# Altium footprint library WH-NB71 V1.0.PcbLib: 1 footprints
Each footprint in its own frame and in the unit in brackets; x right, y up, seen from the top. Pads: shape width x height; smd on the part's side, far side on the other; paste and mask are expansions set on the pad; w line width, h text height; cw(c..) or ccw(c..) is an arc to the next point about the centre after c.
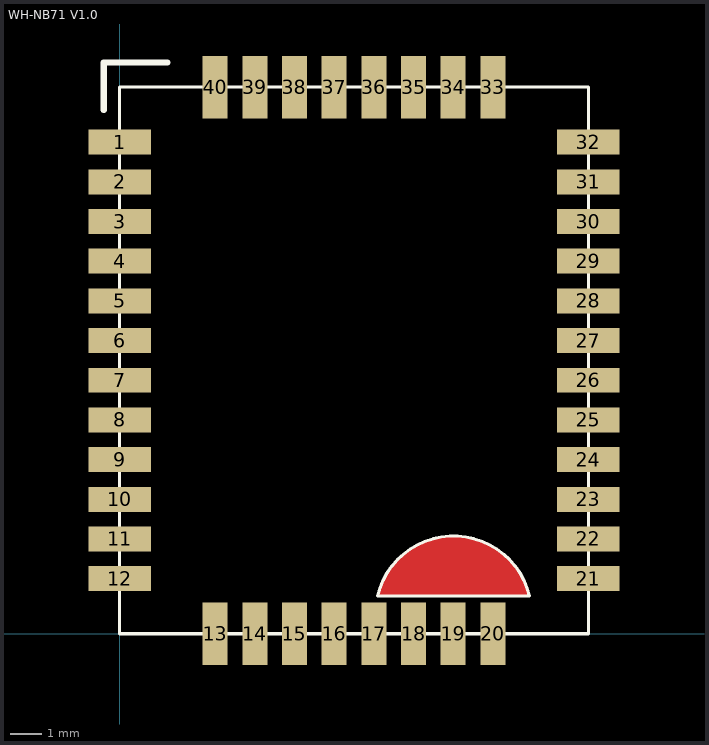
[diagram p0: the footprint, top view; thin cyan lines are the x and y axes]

## WH-NB71 V1.0 [mm]
pads (40):
  rect 2x0.8 smd: 1(0,15.735) 2(0,14.465) 3(0,13.195) 4(0,11.925) 5(0,10.655) 6(0,9.385) 7(0,8.115) 8(0,6.845) 9(0,5.575) 10(0,4.305) 11(0,3.035) 12(0,1.765) 21(15.01,1.765) 22(15.01,3.035) 23(15.01,4.305) 24(15.01,5.575) 25(15.01,6.845) 26(15.01,8.115) 27(15.01,9.385) 28(15.01,10.655) 29(15.01,11.925) 30(15.01,13.195) 31(15.01,14.465) 32(15.01,15.735)
  rect 0.8x2 smd: 13(3.06,0) 14(4.33,0) 15(5.6,0) 16(6.87,0) 17(8.14,0) 18(9.41,0) 19(10.68,0) 20(11.95,0) 33(11.95,17.5) 34(10.68,17.5) 35(9.41,17.5) 36(8.14,17.5) 37(6.87,17.5) 38(5.6,17.5) 39(4.33,17.5) 40(3.06,17.5)
Top Layer:
  pour cut-out: 8.257,1.204 8.484,1.829 8.941,2.438 9.5,2.845 10.16,3.073 10.693,3.124 11.151,3.099 11.887,2.845 12.395,2.464 12.776,2.007 13.005,1.575 13.123,1.203 8.712,1.204
Top Overlay:
  lines w0.1: 13.123,1.203 ccw(c10.69,0.63) 8.257,1.204 13.127,1.204 ; 0,0 0,17.5 15.01,17.5 15.01,0 0,0
  lines w0.2: -0.508,16.764 -0.508,18.288 1.524,18.288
